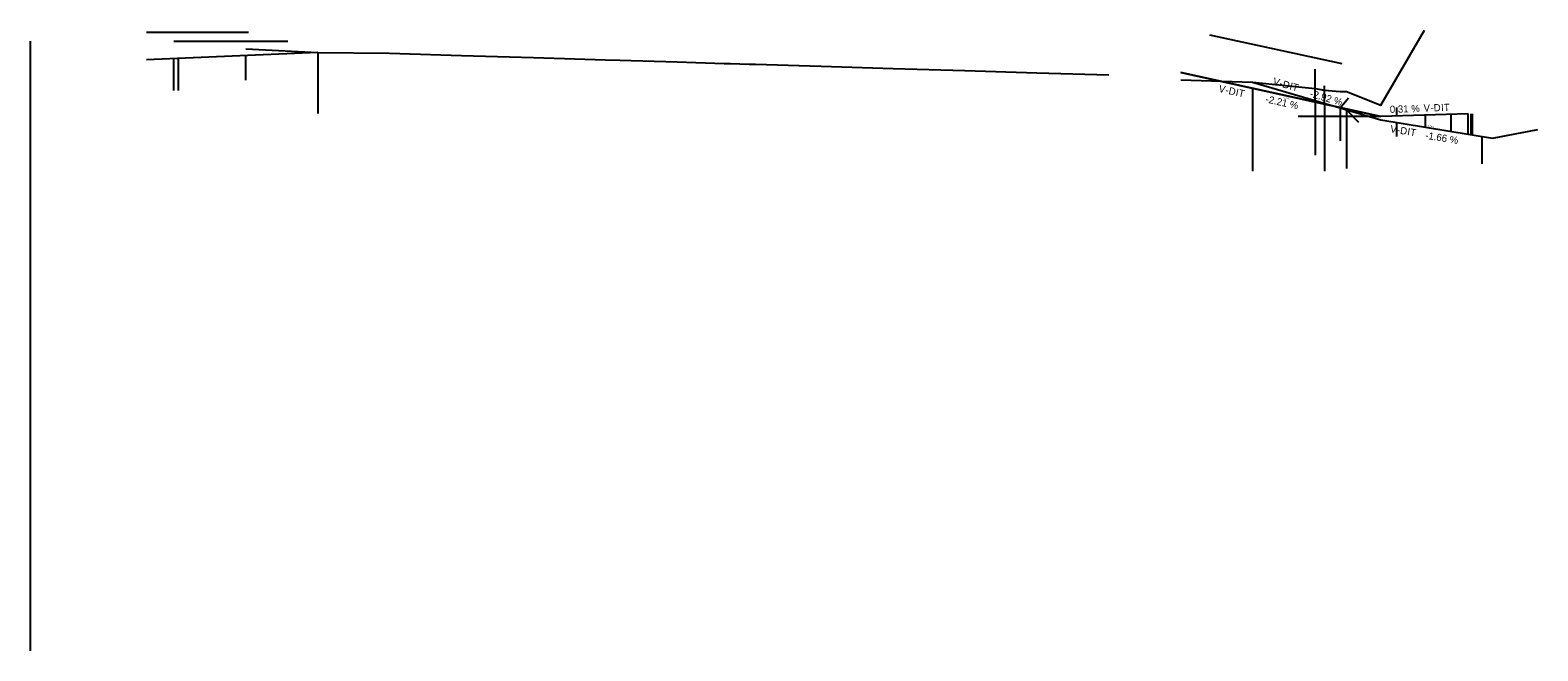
# Model space of a CAD drawing. Extents: x -26 to 1858238, y -23 to 826962.
# Drawn here: x 1857189 to 1858238, y 820055 to 820487 of the extents above; entities that cross this region are included whole.
import ezdxf

# ---------------------------------------------------------------- set-up
doc = ezdxf.new("R2010")
doc.units = 0
for name, color, linetype in [('DESIGN - PROFILE - Drainage - Bridges Drains and Ditches', 7, 'Continuous'), ('DESIGN - PROFILE - Drainage - Bridges Drains and Ditches Text', 7, 'Continuous'), ('DESIGN - SCRATCH - User 1', 7, 'Continuous'), ('DESIGN - SCRATCH - User 3', 7, 'Continuous'), ('DESIGN - TYPICAL - Finished Grade and Subgrade', 7, 'Continuous')]:
    doc.layers.add(name, color=color, linetype=linetype)

msp = doc.modelspace()

# ---------------------------------------------------------------- linework, layer by layer
at = {"layer": 'DESIGN - PROFILE - Drainage - Bridges Drains and Ditches'}
msp.add_line((1857389.4, 820471.1), (1857270.4, 820465.9), dxfattribs=at)
for points in [[(1857989.4, 820457.2), (1858128.6, 820426.5)], [(1858039.4, 820450.3), (1858128.6, 820424.3)], [(1858189.4, 820428.4), (1858128.6, 820426.5)], [(1858128.6, 820424.3), (1858189.4, 820414.2)]]:
    msp.add_lwpolyline(points, dxfattribs=at)
at = {"layer": 'DESIGN - SCRATCH - User 1'}
for p, q in [((1858009.4, 820483.3), (1858101.5, 820463.5)), ((1858128.6, 820426.5), (1857989.4, 820457.2)), ((1858083, 820437.6), (1858083, 820459.5)), ((1858039.4, 820450.3), (1858128.6, 820424.3)), ((1858039.4, 820446.1), (1858039.4, 820388.6)), ((1858089.4, 820435.7), (1858089.4, 820447.9)), ((1858083, 820436.5), (1858083, 820399.7)), ((1858089.4, 820435.1), (1858089.4, 820388.6)), ((1858100.4, 820432.5), (1858106, 820439.5)), ((1858128.6, 820426.5), (1858071.2, 820426.5)), ((1858100.4, 820432.7), (1858100.4, 820409.7)), ((1858104.7, 820431.7), (1858104.7, 820390.3)), ((1858104.7, 820431.2), (1858113, 820422.6)), ((1858128.6, 820424.3), (1858206.2, 820411.4)), ((1858139.4, 820432.7), (1858139.4, 820426.8)), ((1858159.4, 820427.4), (1858159.4, 820419.1)), ((1858177.2, 820428), (1858177.2, 820416.2)), ((1858189.4, 820414.2), (1858189.4, 820428.4)), ((1858191.4, 820413.8), (1858191.4, 820428.4)), ((1858192, 820428.4), (1858192, 820413.7)), ((1858139.4, 820422.5), (1858139.4, 820412.6)), ((1858206.2, 820411.4), (1858237.7, 820417.4)), ((1858199, 820393.6), (1858199, 820412.6))]:
    msp.add_line(p, q, dxfattribs=at)
msp.add_lwpolyline([(1857989.4, 820452.1), (1858039.4, 820450.3), (1858083, 820446.1), (1858089.4, 820444.8), (1858100.4, 820443.9), (1858104.7, 820443.9), (1858128.6, 820434.3), (1858159, 820486.6)], dxfattribs=at)
at = {"layer": 'DESIGN - SCRATCH - User 3'}
for p, q in [((1857289.4, 820444.7), (1857289.4, 820466.7)), ((1857292.4, 820466.8), (1857292.4, 820444.7)), ((1857339.4, 820451.9), (1857339.4, 820468.9)), ((1857389.4, 820471.1), (1857389.4, 820428.7))]:
    msp.add_line(p, q, dxfattribs=at)
msp.add_lwpolyline([(1857339.4, 820473.5), (1857389.4, 820471.1), (1857439.4, 820470.5), (1857489.4, 820469), (1857539.4, 820467.5), (1857589.4, 820466), (1857599.4, 820465.7), (1857639.4, 820464.5), (1857671.9, 820463.5), (1857676.3, 820463.4), (1857689.4, 820463), (1857693.7, 820462.9), (1857739.4, 820461.5), (1857789.4, 820460), (1857839.4, 820458.5), (1857889.4, 820457), (1857939.4, 820455.5)], dxfattribs=at)
at = {"layer": 'DESIGN - TYPICAL - Finished Grade and Subgrade'}
for p, q in [((1857189.4, 820479), (1857189.4, 820054.9)), ((1857270.4, 820485.1), (1857341.3, 820485.1)), ((1857289.4, 820479), (1857368.7, 820479))]:
    msp.add_line(p, q, dxfattribs=at)

# ---------------------------------------------------------------- texts
at = {"layer": 'DESIGN - PROFILE - Drainage - Bridges Drains and Ditches'}
for s, rotation, p in [('V', 347.5463, (1858015.5, 820443.7)), ('D', 347.5463, (1858022.4, 820442.2)), ('I', 347.5463, (1858027.3, 820441.1)), ('T', 347.5463, (1858029.2, 820440.7)), ('V', 343.7397, (1858053.1, 820448.9)), ('-', 343.7397, (1858057.6, 820447.6)), ('D', 343.7397, (1858059.8, 820446.9)), ('I', 343.7397, (1858064.7, 820445.5)), ('T', 343.7397, (1858066.5, 820445)), ('-', 347.5463, (1858020.1, 820442.7)), ('V', 1.794, (1858158.4, 820429.9)), ('D', 1.794, (1858165.4, 820430.1)), ('I', 1.794, (1858170.5, 820430.3)), ('T', 1.794, (1858172.4, 820430.3)), ('-', 1.794, (1858163.1, 820430)), ('V', 350.5653, (1858134.8, 820415.6)), ('-', 350.5653, (1858139.4, 820414.9)), ('D', 350.5653, (1858141.7, 820414.5)), ('I', 350.5653, (1858146.7, 820413.7)), ('T', 350.5653, (1858148.6, 820413.3))]:
    msp.add_text(s, height=5, rotation=rotation, dxfattribs=at).set_placement(p)
at = {"layer": 'DESIGN - PROFILE - Drainage - Bridges Drains and Ditches Text'}
for s, rotation, p in [('-2.21 %', 347.5463, (1858048.1, 820436.4)), ('-2.92 %', 343.7397, (1858078.9, 820440.3)), ('0.31 %', 1.794, (1858134.9, 820429)), ('-1.66 %', 350.5653, (1858159.2, 820411.1))]:
    msp.add_text(s, height=5, rotation=rotation, dxfattribs=at).set_placement(p)
at = {"layer": 'DESIGN - SCRATCH - User 1'}
for s, rotation, p in [('-2.21%', 347.5463, (1858060.7, 820439.4)), ('-1.66%', 350.5653, (1858161, 820419.7))]:
    msp.add_text(s, height=1, rotation=rotation, dxfattribs=at).set_placement(p)

doc.saveas('drawing.dxf')
